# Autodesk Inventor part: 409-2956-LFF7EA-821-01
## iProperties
Created: 2010-09
Part Number: 409-2956-LFF7EA-821-01
Material: 3/8" OD TUBE - SS
Document SubType Name: Modeling
Designer: S. Boerckel
Engineer: Steve Boerckel
Mass: 15.0126 g
Surface Area: 31.4303 cm^2
Volume: 1.85799 cm^3
Density: 8.08 g/cm^3
Description: PRESSURE DIFF TUBE
LGTH: 6.977 in
Author: S. Boerckel
Revision Number: 0
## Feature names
1. Sweep2
